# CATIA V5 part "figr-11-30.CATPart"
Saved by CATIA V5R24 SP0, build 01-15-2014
Part number: Part1
Bounding box of the stored display mesh (mm): x -205 to 53, y -75.374 to 75.374, z 0 to 37.54
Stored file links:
  D:\KAVITA\CATIA V5-6R2014 Project_ Kavita\CATIA V5-6R2014_partfiles\Partfiles\c11_catia_v5-6r2014_prt\figr-11-30.CATPart
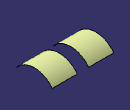
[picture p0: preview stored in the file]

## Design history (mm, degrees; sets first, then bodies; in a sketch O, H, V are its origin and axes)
Set1
  Extrude1: Element1 Sketch1, Lim1 53, Lim2 52, Direction yz-plane
  Translate1: ToTransfor Extrude1, Direction edge of Extrude1, Length 153
Body1 (main body)
  Sketch1 on yz-plane, origin (0, 0, 0), H (0, 1, 0), V (0, 0, 1)
    arc A1 centre (0, -56.4477) radius 94.1675 from (-75.3736, 0) to (75.3736, 0) cw
    point P1 (0, -56.4477)
    point P2 (-75.3736, 0)
    point P3 (75.3736, 0)
    point P4 (0, 37.7198)
    coincidence: P2 H, P3 H, A1 P4, P4 V, P1 V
